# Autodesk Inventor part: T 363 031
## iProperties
Created: 2006-10
Part Number: T 363 031
Material: 1.0330.5
Document SubType Name: Sheet Metal
Designer: I.Baliuc
Manufacturer: Standard
Standards Organization: Custom
Description: Seitenblech, links
Density: 7.84 g/cm^3
Sheet Metal Rule: Standard
Title: Seitenblech, links
Company: Mayer & Müller AG Schaltgeräte
HalbzeugNorm: DIN 1544
Zweck: LE 800 - 3150 A
Author: T.Messerschmitt
Revision Number: 363031
Keywords: 381003
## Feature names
1. Sweeping1
2. Extrusion1
3. Rundung1 [Fillet]
4. Drehung1 [Revolution]
5. Drehung2 [Revolution]
6. Rechteckige Anordnung1 [Rectangular Pattern]
7. Rundung2 [Fillet]
8. Bohrung_Ø10.2 [Hole]
9. Bohrung_Ø14 [Hole]
10. Bohrung_Ø20E9 [Hole]
11. Bohrung_Ø12D10 [Hole]
12. Bohrung_3xØ5 [Hole]
13. Bohrung_Ø14,1 [Hole]
14. Bohrung_Ø6.6 [Hole]
15. Bohrung_Ø3.3 [Hole]
16. Extrusion2
17. Bohrung_Ø5.2 [Hole]
18. Extrusion3
19. Bohrung_Ø6.6x3 [Hole]
20. Extrusion5
21. Bohrung13 [Hole]
22. Rundung4 [Fillet]
23. Extrusion6
24. Bohrung14 [Hole]
25. Rundung5 [Fillet]
26. Rechteckige Anordnung3 [Rectangular Pattern]
27. Extrusion7
28. Bohrung15 [Hole]
29. Rundung6 [Fillet]
30. Bohrung_Ø20_2 [Hole]
31. Grobblech1
32. Grobblech2
33. Biegung1
34. Grobblech3
35. Biegung2
36. Grobblech4
37. Biegung3
38. Grobblech5
39. Biegung4
40. Grobblech6
41. Biegung5
42. Grobblech7
43. Biegung6
44. Grobblech8
45. Biegung7
46. Ausschneiden1
47. Ausschneiden2
48. Ausschneiden3
49. Ausschneiden4
50. Ausschneiden5
51. ExtrusionAbwicklung2
